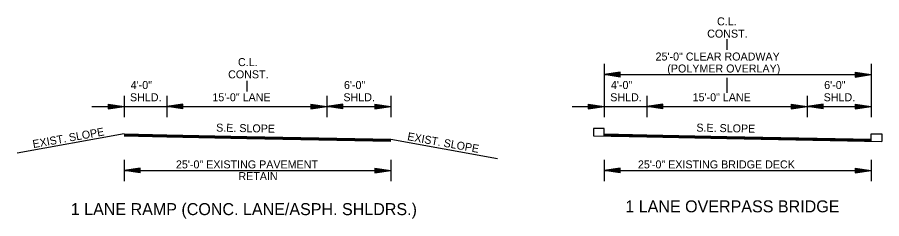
# Model space of a CAD drawing. Extents: x 545241 to 1930787, y -1971772 to 596640.
# Drawn here: x 546851 to 547661, y -1950265 to -1950076 of the extents above; entities that cross this region are included whole.
import ezdxf

# ---------------------------------------------------------------- set-up
doc = ezdxf.new("R2010")
doc.units = 0
doc.layers.add('R_Border', color=7, linetype='Continuous')

msp = doc.modelspace()

# ---------------------------------------------------------------- linework, layer by layer
at = {"layer": 'R_Border'}
for p, q in [((547515.6, -1950096.59), (547515.6, -1950106.59)), ((547400.6, -1950119.76), (547400.6, -1950169.76)), ((547650.6, -1950119.76), (547650.6, -1950169.76)), ((547415.6, -1950127.51), (547400.6, -1950129.76)), ((547400.6, -1950129.76), (547650.6, -1950129.76)), ((547415.6, -1950132.01), (547400.6, -1950129.76)), ((547415.6, -1950127.89), (547403.1, -1950129.76)), ((547415.6, -1950131.64), (547403.1, -1950129.76)), ((547415.6, -1950128.27), (547405.68, -1950129.76)), ((547415.6, -1950131.26), (547405.68, -1950129.76)), ((547415.6, -1950128.65), (547408.18, -1950129.76)), ((547415.6, -1950130.88), (547408.18, -1950129.76)), ((547415.6, -1950129.03), (547410.72, -1950129.76)), ((547415.6, -1950130.49), (547410.72, -1950129.76)), ((547415.6, -1950129.41), (547413.23, -1950129.76)), ((547415.6, -1950130.12), (547413.23, -1950129.76)), ((547415.6, -1950132.01), (547415.6, -1950127.51)), ((547635.6, -1950127.51), (547650.6, -1950129.76)), ((547635.6, -1950127.51), (547635.6, -1950132.01)), ((547635.6, -1950127.89), (547648.09, -1950129.76)), ((547635.6, -1950128.27), (547645.51, -1950129.76)), ((547635.6, -1950128.65), (547643.01, -1950129.76)), ((547635.6, -1950129.04), (547640.47, -1950129.76)), ((547635.6, -1950129.41), (547637.97, -1950129.76)), ((547635.6, -1950132.01), (547650.6, -1950129.76)), ((547635.6, -1950130.5), (547640.47, -1950129.76)), ((547635.6, -1950131.26), (547645.51, -1950129.76)), ((547635.6, -1950131.64), (547648.09, -1950129.76)), ((547635.6, -1950130.88), (547643.01, -1950129.76)), ((547635.6, -1950130.12), (547637.97, -1950129.76)), ((547065.6, -1950135.51), (547065.6, -1950145.51)), ((547515.6, -1950132.76), (547515.6, -1950146.76)), ((546950.6, -1950149.76), (546950.6, -1950169.76)), ((546990.6, -1950149.76), (546990.6, -1950169.76)), ((547140.6, -1950149.76), (547140.6, -1950169.76)), ((547200.6, -1950149.76), (547200.6, -1950169.76)), ((547440.6, -1950149.76), (547440.6, -1950169.76)), ((547590.6, -1950149.76), (547590.6, -1950169.76)), ((546920.6, -1950159.76), (547200.6, -1950159.76)), ((546935.6, -1950157.51), (546950.6, -1950159.76)), ((546935.6, -1950157.51), (546935.6, -1950162.01)), ((546935.6, -1950157.89), (546948.09, -1950159.76)), ((546935.6, -1950158.27), (546945.51, -1950159.76)), ((546935.6, -1950158.65), (546943.01, -1950159.76)), ((546935.6, -1950159.04), (546940.47, -1950159.76)), ((546935.6, -1950159.41), (546937.97, -1950159.76)), ((546935.6, -1950162.01), (546950.6, -1950159.76)), ((546935.6, -1950160.5), (546940.47, -1950159.76)), ((546935.6, -1950161.26), (546945.51, -1950159.76)), ((546935.6, -1950161.64), (546948.09, -1950159.76)), ((546935.6, -1950160.88), (546943.01, -1950159.76)), ((546935.6, -1950160.12), (546937.97, -1950159.76)), ((547005.6, -1950157.51), (546990.6, -1950159.76)), ((547005.6, -1950162.01), (546990.6, -1950159.76)), ((547005.6, -1950157.89), (546993.1, -1950159.76)), ((547005.6, -1950161.64), (546993.1, -1950159.76)), ((547005.6, -1950158.27), (546995.68, -1950159.76)), ((547005.6, -1950161.26), (546995.68, -1950159.76)), ((547005.6, -1950158.65), (546998.18, -1950159.76)), ((547005.6, -1950160.88), (546998.18, -1950159.76)), ((547005.6, -1950159.03), (547000.72, -1950159.76)), ((547005.6, -1950160.49), (547000.72, -1950159.76)), ((547005.6, -1950159.41), (547003.23, -1950159.76)), ((547005.6, -1950160.12), (547003.23, -1950159.76)), ((547005.6, -1950162.01), (547005.6, -1950157.51)), ((547125.6, -1950157.51), (547140.6, -1950159.76)), ((547125.6, -1950157.51), (547125.6, -1950162.01)), ((547125.6, -1950157.89), (547138.09, -1950159.76)), ((547125.6, -1950158.27), (547135.51, -1950159.76)), ((547125.6, -1950158.65), (547133.01, -1950159.76)), ((547125.6, -1950159.04), (547130.47, -1950159.76)), ((547125.6, -1950159.41), (547127.97, -1950159.76)), ((547125.6, -1950162.01), (547140.6, -1950159.76)), ((547125.6, -1950160.5), (547130.47, -1950159.76)), ((547125.6, -1950161.26), (547135.51, -1950159.76)), ((547125.6, -1950161.64), (547138.09, -1950159.76)), ((547125.6, -1950160.88), (547133.01, -1950159.76)), ((547125.6, -1950160.12), (547127.97, -1950159.76)), ((547155.6, -1950157.51), (547140.6, -1950159.76)), ((547155.6, -1950162.01), (547140.6, -1950159.76)), ((547155.6, -1950157.89), (547143.1, -1950159.76)), ((547155.6, -1950161.64), (547143.1, -1950159.76)), ((547155.6, -1950158.27), (547145.68, -1950159.76)), ((547155.6, -1950161.26), (547145.68, -1950159.76)), ((547155.6, -1950158.65), (547148.18, -1950159.76)), ((547155.6, -1950160.88), (547148.18, -1950159.76)), ((547155.6, -1950159.03), (547150.72, -1950159.76)), ((547155.6, -1950160.49), (547150.72, -1950159.76)), ((547155.6, -1950159.41), (547153.23, -1950159.76)), ((547155.6, -1950160.12), (547153.23, -1950159.76)), ((547155.6, -1950162.01), (547155.6, -1950157.51)), ((547185.6, -1950157.51), (547200.6, -1950159.76)), ((547185.6, -1950157.51), (547185.6, -1950162.01)), ((547185.6, -1950157.89), (547198.09, -1950159.76)), ((547185.6, -1950158.27), (547195.51, -1950159.76)), ((547185.6, -1950158.65), (547193.01, -1950159.76)), ((547185.6, -1950159.04), (547190.47, -1950159.76)), ((547185.6, -1950159.41), (547187.97, -1950159.76)), ((547185.6, -1950162.01), (547200.6, -1950159.76)), ((547185.6, -1950160.5), (547190.47, -1950159.76)), ((547185.6, -1950161.26), (547195.51, -1950159.76)), ((547185.6, -1950161.64), (547198.09, -1950159.76)), ((547185.6, -1950160.88), (547193.01, -1950159.76)), ((547185.6, -1950160.12), (547187.97, -1950159.76)), ((547370.6, -1950159.76), (547650.6, -1950159.76)), ((547385.6, -1950157.51), (547400.6, -1950159.76)), ((547385.6, -1950157.51), (547385.6, -1950162.01)), ((547385.6, -1950157.89), (547398.09, -1950159.76)), ((547385.6, -1950158.27), (547395.51, -1950159.76)), ((547385.6, -1950158.65), (547393.01, -1950159.76)), ((547385.6, -1950159.04), (547390.47, -1950159.76)), ((547385.6, -1950159.41), (547387.97, -1950159.76)), ((547385.6, -1950162.01), (547400.6, -1950159.76)), ((547385.6, -1950160.5), (547390.47, -1950159.76)), ((547385.6, -1950161.26), (547395.51, -1950159.76)), ((547385.6, -1950161.64), (547398.09, -1950159.76)), ((547385.6, -1950160.88), (547393.01, -1950159.76)), ((547385.6, -1950160.12), (547387.97, -1950159.76)), ((547455.6, -1950157.51), (547440.6, -1950159.76)), ((547455.6, -1950162.01), (547440.6, -1950159.76)), ((547455.6, -1950157.89), (547443.1, -1950159.76)), ((547455.6, -1950161.64), (547443.1, -1950159.76)), ((547455.6, -1950158.27), (547445.68, -1950159.76)), ((547455.6, -1950161.26), (547445.68, -1950159.76)), ((547455.6, -1950158.65), (547448.18, -1950159.76)), ((547455.6, -1950160.88), (547448.18, -1950159.76)), ((547455.6, -1950159.03), (547450.72, -1950159.76)), ((547455.6, -1950160.49), (547450.72, -1950159.76)), ((547455.6, -1950159.41), (547453.23, -1950159.76)), ((547455.6, -1950160.12), (547453.23, -1950159.76)), ((547455.6, -1950162.01), (547455.6, -1950157.51)), ((547575.6, -1950157.51), (547590.6, -1950159.76)), ((547575.6, -1950157.51), (547575.6, -1950162.01)), ((547575.6, -1950157.89), (547588.09, -1950159.76)), ((547575.6, -1950158.27), (547585.51, -1950159.76)), ((547575.6, -1950158.65), (547583.01, -1950159.76)), ((547575.6, -1950159.04), (547580.47, -1950159.76)), ((547575.6, -1950159.41), (547577.97, -1950159.76)), ((547575.6, -1950162.01), (547590.6, -1950159.76)), ((547575.6, -1950160.5), (547580.47, -1950159.76)), ((547575.6, -1950161.26), (547585.51, -1950159.76)), ((547575.6, -1950161.64), (547588.09, -1950159.76)), ((547575.6, -1950160.88), (547583.01, -1950159.76)), ((547575.6, -1950160.12), (547577.97, -1950159.76)), ((547605.6, -1950157.51), (547590.6, -1950159.76)), ((547605.6, -1950162.01), (547590.6, -1950159.76)), ((547605.6, -1950157.89), (547593.1, -1950159.76)), ((547605.6, -1950161.64), (547593.1, -1950159.76)), ((547605.6, -1950158.27), (547595.68, -1950159.76)), ((547605.6, -1950161.26), (547595.68, -1950159.76)), ((547605.6, -1950158.65), (547598.18, -1950159.76)), ((547605.6, -1950160.88), (547598.18, -1950159.76)), ((547605.6, -1950159.03), (547600.72, -1950159.76)), ((547605.6, -1950160.49), (547600.72, -1950159.76)), ((547605.6, -1950159.41), (547603.23, -1950159.76)), ((547605.6, -1950160.12), (547603.23, -1950159.76)), ((547605.6, -1950162.01), (547605.6, -1950157.51)), ((547635.6, -1950157.51), (547650.6, -1950159.76)), ((547635.6, -1950157.51), (547635.6, -1950162.01)), ((547635.6, -1950157.89), (547648.09, -1950159.76)), ((547635.6, -1950158.27), (547645.51, -1950159.76)), ((547635.6, -1950158.65), (547643.01, -1950159.76)), ((547635.6, -1950159.04), (547640.47, -1950159.76)), ((547635.6, -1950159.41), (547637.97, -1950159.76)), ((547635.6, -1950162.01), (547650.6, -1950159.76)), ((547635.6, -1950160.5), (547640.47, -1950159.76)), ((547635.6, -1950161.26), (547645.51, -1950159.76)), ((547635.6, -1950161.64), (547648.09, -1950159.76)), ((547635.6, -1950160.88), (547643.01, -1950159.76)), ((547635.6, -1950160.12), (547637.97, -1950159.76)), ((546950.6, -1950185.46), (546850.6, -1950203.46)), ((547200.6, -1950190.46), (547300.6, -1950208.46)), ((546950.6, -1950209.76), (546950.6, -1950229.76)), ((547200.6, -1950209.76), (547200.6, -1950229.76)), ((547400.6, -1950209.76), (547400.6, -1950229.76)), ((547650.6, -1950209.76), (547650.6, -1950229.76)), ((546965.6, -1950217.51), (546950.6, -1950219.76)), ((546950.6, -1950219.76), (547200.6, -1950219.76)), ((546965.6, -1950222.01), (546950.6, -1950219.76)), ((546965.6, -1950217.89), (546953.1, -1950219.76)), ((546965.6, -1950221.64), (546953.1, -1950219.76)), ((546965.6, -1950218.27), (546955.68, -1950219.76)), ((546965.6, -1950221.26), (546955.68, -1950219.76)), ((546965.6, -1950218.65), (546958.18, -1950219.76)), ((546965.6, -1950220.88), (546958.18, -1950219.76)), ((546965.6, -1950219.03), (546960.72, -1950219.76)), ((546965.6, -1950220.49), (546960.72, -1950219.76)), ((546965.6, -1950219.41), (546963.23, -1950219.76)), ((546965.6, -1950220.12), (546963.23, -1950219.76)), ((546965.6, -1950222.01), (546965.6, -1950217.51)), ((547185.6, -1950217.51), (547200.6, -1950219.76)), ((547185.6, -1950217.51), (547185.6, -1950222.01)), ((547185.6, -1950217.89), (547198.09, -1950219.76)), ((547185.6, -1950218.27), (547195.51, -1950219.76)), ((547185.6, -1950218.65), (547193.01, -1950219.76)), ((547185.6, -1950219.04), (547190.47, -1950219.76)), ((547185.6, -1950219.41), (547187.97, -1950219.76)), ((547185.6, -1950222.01), (547200.6, -1950219.76)), ((547185.6, -1950220.5), (547190.47, -1950219.76)), ((547185.6, -1950221.26), (547195.51, -1950219.76)), ((547185.6, -1950221.64), (547198.09, -1950219.76)), ((547185.6, -1950220.88), (547193.01, -1950219.76)), ((547185.6, -1950220.12), (547187.97, -1950219.76)), ((547415.6, -1950217.51), (547400.6, -1950219.76)), ((547400.6, -1950219.76), (547650.6, -1950219.76)), ((547415.6, -1950222.01), (547400.6, -1950219.76)), ((547415.6, -1950217.89), (547403.1, -1950219.76)), ((547415.6, -1950221.64), (547403.1, -1950219.76)), ((547415.6, -1950218.27), (547405.68, -1950219.76)), ((547415.6, -1950221.26), (547405.68, -1950219.76)), ((547415.6, -1950218.65), (547408.18, -1950219.76)), ((547415.6, -1950220.88), (547408.18, -1950219.76)), ((547415.6, -1950219.03), (547410.72, -1950219.76)), ((547415.6, -1950220.49), (547410.72, -1950219.76)), ((547415.6, -1950219.41), (547413.23, -1950219.76)), ((547415.6, -1950220.12), (547413.23, -1950219.76)), ((547415.6, -1950222.01), (547415.6, -1950217.51)), ((547635.6, -1950217.51), (547650.6, -1950219.76)), ((547635.6, -1950217.51), (547635.6, -1950222.01)), ((547635.6, -1950217.89), (547648.09, -1950219.76)), ((547635.6, -1950218.27), (547645.51, -1950219.76)), ((547635.6, -1950218.65), (547643.01, -1950219.76)), ((547635.6, -1950219.04), (547640.47, -1950219.76)), ((547635.6, -1950219.41), (547637.97, -1950219.76)), ((547635.6, -1950222.01), (547650.6, -1950219.76)), ((547635.6, -1950220.5), (547640.47, -1950219.76)), ((547635.6, -1950221.26), (547645.51, -1950219.76)), ((547635.6, -1950221.64), (547648.09, -1950219.76)), ((547635.6, -1950220.88), (547643.01, -1950219.76)), ((547635.6, -1950220.12), (547637.97, -1950219.76))]:
    msp.add_line(p, q, dxfattribs=at)
for points in [[(546950.6, -1950185.46), (546990.6, -1950186.26), (547065.6, -1950187.76), (547200.6, -1950190.46)], [(546950.6, -1950185.76), (546990.6, -1950186.56), (547065.6, -1950188.06), (547200.6, -1950190.76)], [(546950.6, -1950186.06), (546990.6, -1950186.86), (547065.6, -1950188.36), (547200.6, -1950191.06)], [(546950.6, -1950186.36), (546990.6, -1950187.16), (547065.6, -1950188.66), (547200.6, -1950191.36)], [(546950.6, -1950186.66), (546990.6, -1950187.46), (547065.6, -1950188.96), (547200.6, -1950191.66)], [(546950.6, -1950186.96), (546990.6, -1950187.76), (547065.6, -1950189.26), (547200.6, -1950191.96)], [(546950.6, -1950187.26), (546990.6, -1950188.06), (547065.6, -1950189.56), (547200.6, -1950192.26)], [(547400.6, -1950186.96), (547400.6, -1950180.46), (547390.6, -1950180.46), (547390.6, -1950187.06)], [(547390.6, -1950187.06), (547440.6, -1950188.06), (547515.6, -1950189.56), (547660.6, -1950192.46)], [(547400.6, -1950185.46), (547440.6, -1950186.26), (547515.6, -1950187.76), (547650.6, -1950190.46)], [(547400.6, -1950185.76), (547440.6, -1950186.56), (547515.6, -1950188.06), (547650.6, -1950190.76)], [(547400.6, -1950186.06), (547440.6, -1950186.86), (547515.6, -1950188.36), (547650.6, -1950191.06)], [(547400.6, -1950186.36), (547440.6, -1950187.16), (547515.6, -1950188.66), (547650.6, -1950191.36)], [(547400.6, -1950186.66), (547440.6, -1950187.46), (547515.6, -1950188.96), (547650.6, -1950191.66)], [(547400.6, -1950186.96), (547440.6, -1950187.76), (547515.6, -1950189.26), (547650.6, -1950191.96)], [(547650.6, -1950191.96), (547650.6, -1950185.46), (547660.6, -1950185.46), (547660.6, -1950192.46)]]:
    msp.add_lwpolyline(points, dxfattribs=at)

# ---------------------------------------------------------------- texts
for s, height, p in [('C.L.', 7.5, (547506.26, -1950083.54)), ('CONST.', 7.5, (547497.05, -1950095.04)), ('C.L.', 7.5, (547057.37, -1950121.76)), ('25\'-0" CLEAR ROADWAY', 7.5, (547448.69, -1950116.51)), ('(POLYMER OVERLAY)', 7.5, (547459.67, -1950127.76)), ('CONST.', 7.5, (547048.16, -1950133.26)), ('4\'-0"', 7.5, (546956.86, -1950143.26)), ('6\'-0"', 7.5, (547156.69, -1950143.26)), ('4\'-0"', 7.5, (547406.86, -1950143.26)), ('6\'-0"', 7.5, (547606.69, -1950143.26)), ('SHLD.', 7.5, (546956.19, -1950154.76)), ('15\'-0" LANE', 7.5, (547033.41, -1950154.76)), ('SHLD.', 7.5, (547156.19, -1950154.76)), ('SHLD.', 7.5, (547406.19, -1950154.76)), ('15\'-0" LANE', 7.5, (547483.41, -1950154.76)), ('SHLD.', 7.5, (547606.19, -1950154.76)), ('25\'-0" EXISTING PAVEMENT', 7.5, (546999.27, -1950217.76)), ('25\'-0" EXISTING BRIDGE DECK', 7.5, (547432.15, -1950217.76)), ('RETAIN', 7.5, (547057.79, -1950228.76)), ('1 LANE RAMP (CONC. LANE/ASPH. SHLDRS.)', 11.25, (546900.73, -1950261.61)), ('1 LANE OVERPASS BRIDGE', 11.25, (547420.35, -1950259))]:
    msp.add_text(s, height=height, dxfattribs=at).set_placement(p)
for s, rotation, p in [('EXIST. SLOPE', 10.204, (546865.66, -1950198.75)), ('S.E. SLOPE', 358.85424, (547036.86, -1950183.19)), ('S.E. SLOPE', 358.85424, (547486.86, -1950183.19)), ('EXIST. SLOPE', 349.796, (547215.66, -1950191.18))]:
    msp.add_text(s, height=7.5, rotation=rotation, dxfattribs=at).set_placement(p)

doc.saveas('drawing.dxf')
